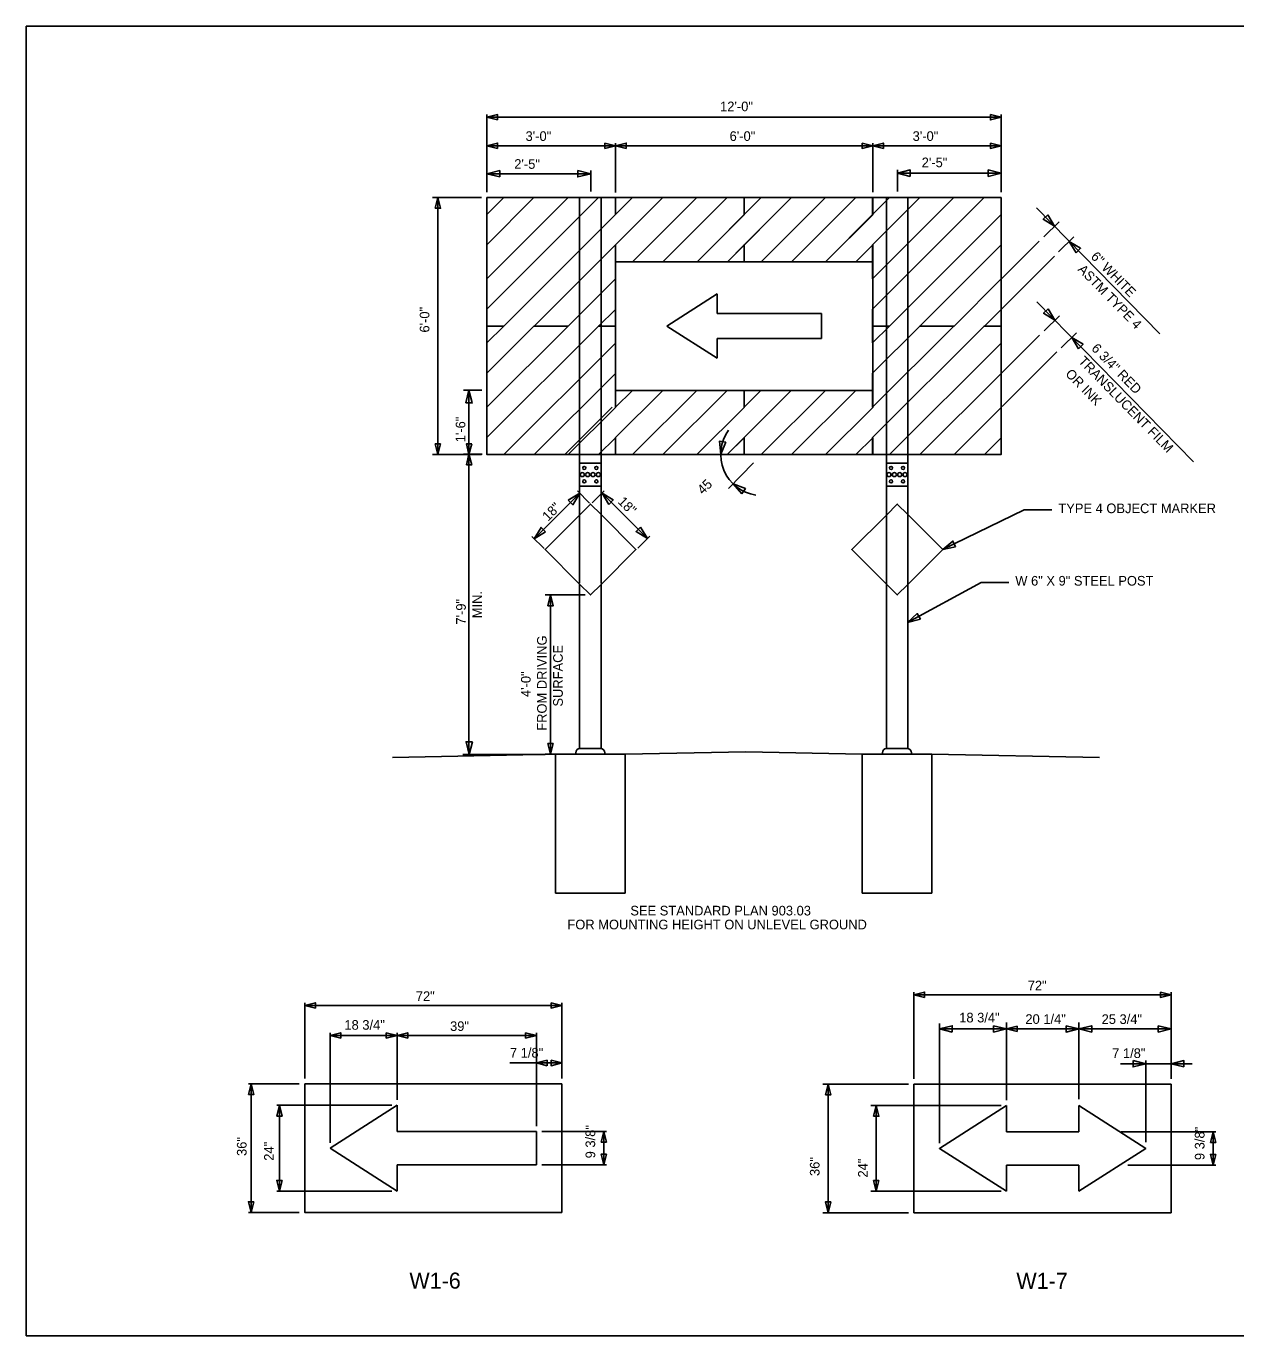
# Model space of a CAD drawing. Extents: x -439.1 to -407.9, y -458.1 to -437.7.
# Drawn here: x -439.11 to -420.29, y -458.05 to -437.68 of the extents above; entities that cross this region are included whole.
import ezdxf

# ---------------------------------------------------------------- set-up
doc = ezdxf.new("R2010")
doc.units = 0
for name, color, linetype in [('Draft_Named_Boundary', 7, 'Continuous'), ('Level 4', 7, 'Continuous'), ('Level 45', 7, 'Continuous')]:
    doc.layers.add(name, color=color, linetype=linetype)

msp = doc.modelspace()

# ---------------------------------------------------------------- linework, layer by layer
at = {"layer": 'Draft_Named_Boundary'}
msp.add_lwpolyline([(-439.109, -458.051), (-407.859, -458.051), (-407.859, -437.676), (-439.109, -437.676)], close=True, dxfattribs=at)
at = {"layer": 'Level 4'}
for p, q in [((-431.681, -440.342), (-431.943, -440.604)), ((-431.21, -440.342), (-431.943, -441.075)), ((-430.679, -440.342), (-431.943, -441.605)), ((-430.208, -440.342), (-431.943, -442.077)), ((-429.678, -440.342), (-429.941, -440.605)), ((-428.676, -440.342), (-429.675, -441.342)), ((-428.204, -440.342), (-429.204, -441.342)), ((-427.678, -440.342), (-427.941, -440.605)), ((-427.206, -440.342), (-427.941, -441.076)), ((-426.676, -440.342), (-427.675, -441.342)), ((-426.204, -440.342), (-427.204, -441.342)), ((-425.681, -440.342), (-425.943, -440.604)), ((-425.21, -440.342), (-425.943, -441.075)), ((-424.679, -440.342), (-425.943, -441.605)), ((-424.208, -440.342), (-425.943, -442.077)), ((-423.393, -440.502), (-421.475, -442.46)), ((-429.943, -440.607), (-431.678, -442.342)), ((-427.941, -440.609), (-428.674, -441.342)), ((-425.941, -440.609), (-426.674, -441.342)), ((-423.943, -440.607), (-425.678, -442.342)), ((-423.28, -440.951), (-423.042, -440.718)), ((-427.941, -441.08), (-428.202, -441.342)), ((-425.941, -441.08), (-426.202, -441.342)), ((-423.943, -441.079), (-425.206, -442.342)), ((-423.938, -441.607), (-423.352, -441.021)), ((-423.049, -441.187), (-422.811, -440.954)), ((-423.938, -442.079), (-423.112, -441.253)), ((-429.943, -441.609), (-430.676, -442.342)), ((-423.943, -441.609), (-424.676, -442.342)), ((-428.362, -441.842), (-429.144, -442.342)), ((-428.362, -442.146), (-428.362, -441.842)), ((-429.943, -442.081), (-430.204, -442.342)), ((-423.386, -441.964), (-420.951, -444.452)), ((-426.737, -442.146), (-428.362, -442.146)), ((-426.737, -442.537), (-426.737, -442.146)), ((-423.273, -442.413), (-423.035, -442.18)), ((-431.681, -442.342), (-431.943, -442.604)), ((-431.21, -442.342), (-431.943, -443.075)), ((-430.679, -442.342), (-431.943, -443.605)), ((-430.208, -442.342), (-431.943, -444.077)), ((-429.144, -442.342), (-428.362, -442.842)), ((-428.362, -442.842), (-428.362, -442.537)), ((-428.362, -442.537), (-426.737, -442.537)), ((-425.681, -442.342), (-425.943, -442.604)), ((-425.21, -442.342), (-425.943, -443.075)), ((-424.679, -442.342), (-425.943, -443.605)), ((-424.208, -442.342), (-425.943, -444.077)), ((-423.931, -443.069), (-423.344, -442.483)), ((-423.011, -442.681), (-422.773, -442.447)), ((-429.943, -442.607), (-431.678, -444.342)), ((-423.943, -442.607), (-425.678, -444.342)), ((-423.926, -443.595), (-423.075, -442.744)), ((-429.943, -443.079), (-431.206, -444.342)), ((-423.943, -443.079), (-425.206, -444.342)), ((-429.679, -443.342), (-429.941, -443.603)), ((-429.208, -443.342), (-429.941, -444.075)), ((-428.677, -443.342), (-429.678, -444.342)), ((-428.206, -443.342), (-429.206, -444.342)), ((-427.679, -443.342), (-427.941, -443.603)), ((-427.208, -443.342), (-427.941, -444.075)), ((-426.677, -443.342), (-427.678, -444.342)), ((-426.206, -443.342), (-427.206, -444.342)), ((-429.993, -443.603), (-430.726, -444.336)), ((-427.941, -443.607), (-428.676, -444.342)), ((-425.941, -443.607), (-426.676, -444.342)), ((-423.943, -443.609), (-424.676, -444.342)), ((-429.943, -444.081), (-430.204, -444.342)), ((-427.941, -444.078), (-428.204, -444.342)), ((-425.941, -444.078), (-426.204, -444.342)), ((-423.943, -444.081), (-424.204, -444.342)), ((-432.221, -444.342), (-432.221, -448.957)), ((-430.501, -444.476), (-430.501, -444.83)), ((-430.167, -444.476), (-430.501, -444.476)), ((-430.167, -444.476), (-430.167, -444.83)), ((-427.795, -444.47), (-428.182, -444.866)), ((-425.729, -444.476), (-425.729, -444.83)), ((-425.729, -444.476), (-425.396, -444.476)), ((-425.396, -444.476), (-425.396, -444.83)), ((-430.167, -444.83), (-430.501, -444.83)), ((-425.729, -444.83), (-425.396, -444.83)), ((-430.874, -449.004), (-433.413, -449.055)), ((-430.584, -449.004), (-431.035, -449.004)), ((-430.874, -449.004), (-430.874, -451.164)), ((-430.874, -449.004), (-429.794, -449.004)), ((-430.561, -448.979), (-430.561, -449.004)), ((-430.496, -448.914), (-430.174, -448.914)), ((-430.447, -448.914), (-430.222, -448.914)), ((-430.11, -448.979), (-430.11, -449.004)), ((-429.794, -449.004), (-429.794, -451.164)), ((-426.103, -449.004), (-426.103, -451.164)), ((-426.103, -449.004), (-425.023, -449.004)), ((-425.789, -448.979), (-425.789, -449.004)), ((-425.725, -448.914), (-425.403, -448.914)), ((-425.675, -448.914), (-425.45, -448.914)), ((-425.338, -448.979), (-425.338, -449.004)), ((-425.023, -449.004), (-422.414, -449.055)), ((-425.023, -449.004), (-425.023, -451.164)), ((-430.874, -451.164), (-429.794, -451.164)), ((-426.103, -451.164), (-425.023, -451.164)), ((-433.34, -454.465), (-434.382, -455.132)), ((-433.34, -454.871), (-433.34, -454.465)), ((-423.862, -454.469), (-424.904, -455.136)), ((-423.862, -454.875), (-423.862, -454.469)), ((-422.733, -454.875), (-422.733, -454.469)), ((-422.733, -454.469), (-421.691, -455.136)), ((-431.173, -454.871), (-433.34, -454.871)), ((-431.173, -455.392), (-431.173, -454.871)), ((-422.733, -454.875), (-423.862, -454.875)), ((-423.862, -454.875), (-422.733, -454.875)), ((-434.382, -455.132), (-433.34, -455.799)), ((-424.904, -455.136), (-423.862, -455.802)), ((-424.9, -455.138), (-424.9, -455.133)), ((-421.691, -455.136), (-422.733, -455.802)), ((-421.695, -455.138), (-421.695, -455.133)), ((-433.34, -455.799), (-433.34, -455.392)), ((-433.34, -455.392), (-431.173, -455.392)), ((-423.862, -455.802), (-423.862, -455.396)), ((-423.862, -455.396), (-422.733, -455.396)), ((-422.733, -455.396), (-423.862, -455.396)), ((-422.733, -455.802), (-422.733, -455.396))]:
    msp.add_line(p, q, dxfattribs=at)
for points in [[(-431.943, -440.342), (-423.943, -440.342), (-423.943, -444.342), (-431.943, -444.342)], [(-431.943, -442.077), (-431.943, -442.342), (-431.678, -442.342), (-429.943, -440.607), (-429.943, -440.342), (-430.208, -440.342)], [(-431.943, -441.605), (-431.943, -441.075), (-431.21, -440.342), (-430.679, -440.342)], [(-431.943, -440.604), (-431.943, -440.342), (-431.681, -440.342)], [(-430.167, -440.342), (-430.167, -444.337), (-430.501, -444.337), (-430.501, -440.342)], [(-429.678, -440.342), (-429.941, -440.342), (-429.941, -440.605)], [(-429.206, -440.342), (-429.941, -441.076), (-429.941, -441.342), (-429.675, -441.342), (-428.676, -440.342)], [(-428.204, -440.342), (-427.678, -440.342), (-428.674, -441.342), (-429.204, -441.342)], [(-428.202, -441.342), (-427.675, -441.342), (-426.676, -440.342), (-427.206, -440.342)], [(-427.204, -441.342), (-426.674, -441.342), (-425.943, -440.604), (-425.943, -440.342), (-426.204, -440.342)], [(-425.943, -442.077), (-425.943, -442.342), (-425.678, -442.342), (-423.943, -440.607), (-423.943, -440.342), (-424.208, -440.342)], [(-425.943, -441.605), (-425.943, -441.075), (-425.21, -440.342), (-424.679, -440.342)], [(-425.943, -440.604), (-425.943, -440.342), (-425.681, -440.342)], [(-425.396, -440.342), (-425.396, -444.338), (-425.729, -444.338), (-425.729, -440.342)], [(-423.218, -440.61), (-423.113, -440.788), (-423.289, -440.68)], [(-431.206, -442.342), (-430.676, -442.342), (-429.943, -441.609), (-429.943, -441.079)], [(-428.202, -441.342), (-427.941, -441.342), (-427.941, -441.08)], [(-426.202, -441.342), (-425.941, -441.342), (-425.941, -441.08)], [(-425.206, -442.342), (-424.676, -442.342), (-423.943, -441.609), (-423.943, -441.079)], [(-422.778, -441.201), (-422.883, -441.024), (-422.707, -441.131)], [(-429.941, -441.342), (-425.941, -441.342), (-425.941, -443.342), (-429.941, -443.342)], [(-430.204, -442.342), (-429.943, -442.342), (-429.943, -442.081)], [(-424.204, -442.342), (-423.943, -442.342), (-423.943, -442.081)], [(-423.21, -442.072), (-423.106, -442.25), (-423.282, -442.142)], [(-431.943, -444.077), (-431.943, -444.342), (-431.678, -444.342), (-429.943, -442.607), (-429.943, -442.342), (-430.208, -442.342)], [(-431.943, -443.605), (-431.943, -443.075), (-431.21, -442.342), (-430.679, -442.342)], [(-431.943, -442.604), (-431.943, -442.342), (-431.681, -442.342)], [(-425.943, -444.077), (-425.943, -444.342), (-425.678, -444.342), (-423.943, -442.607), (-423.943, -442.342), (-424.208, -442.342)], [(-425.943, -443.605), (-425.943, -443.075), (-425.21, -442.342), (-424.679, -442.342)], [(-425.943, -442.604), (-425.943, -442.342), (-425.681, -442.342)], [(-422.74, -442.695), (-422.845, -442.517), (-422.669, -442.625)], [(-431.206, -444.342), (-430.676, -444.342), (-429.943, -443.609), (-429.943, -443.079)], [(-425.206, -444.342), (-424.676, -444.342), (-423.943, -443.609), (-423.943, -443.079)], [(-429.941, -443.603), (-429.941, -443.342), (-429.679, -443.342)], [(-429.941, -444.075), (-429.208, -443.342), (-428.677, -443.342), (-429.678, -444.342), (-429.941, -444.342)], [(-429.206, -444.342), (-428.676, -444.342), (-427.941, -443.607), (-427.941, -443.342), (-428.206, -443.342)], [(-428.204, -444.342), (-427.678, -444.342), (-426.677, -443.342), (-427.208, -443.342)], [(-427.941, -443.603), (-427.941, -443.342), (-427.679, -443.342)], [(-427.206, -444.342), (-426.676, -444.342), (-425.941, -443.607), (-425.941, -443.342), (-426.206, -443.342)], [(-430.204, -444.342), (-429.943, -444.342), (-429.943, -444.081)], [(-428.224, -444.146), (-428.305, -444.335), (-428.323, -444.13)], [(-425.941, -444.078), (-426.204, -444.342), (-425.943, -444.342)], [(-424.204, -444.342), (-423.943, -444.342), (-423.943, -444.081)], [(-427.979, -444.951), (-428.112, -444.795), (-427.921, -444.87)], [(-424.651, -445.776), (-424.852, -445.818), (-424.694, -445.686)], [(-425.199, -446.903), (-425.399, -446.955), (-425.247, -446.815)], [(-434.777, -454.132), (-430.777, -454.132), (-430.777, -456.132), (-434.777, -456.132)], [(-425.299, -454.136), (-421.299, -454.136), (-421.299, -456.136), (-425.299, -456.136)]]:
    msp.add_lwpolyline(points, close=True, dxfattribs=at)
for points in [[(-429.206, -440.342), (-429.941, -441.076), (-429.941, -441.342), (-429.675, -441.342), (-428.676, -440.342)], [(-429.678, -440.342), (-429.941, -440.605), (-429.941, -440.342)], [(-428.204, -440.342), (-429.204, -441.342), (-428.674, -441.342), (-427.941, -440.609), (-427.941, -440.342)], [(-427.206, -440.342), (-427.941, -441.076), (-427.941, -441.342), (-427.675, -441.342), (-426.676, -440.342)], [(-427.678, -440.342), (-427.941, -440.605), (-427.941, -440.342)], [(-426.204, -440.342), (-427.204, -441.342), (-426.674, -441.342), (-425.941, -440.609), (-425.941, -440.342)], [(-429.941, -444.342), (-429.941, -444.075), (-429.208, -443.342), (-428.677, -443.342), (-429.678, -444.342)], [(-428.676, -444.342), (-427.941, -443.607), (-427.941, -443.342), (-428.206, -443.342), (-429.206, -444.342)], [(-427.941, -444.342), (-427.941, -444.075), (-427.208, -443.342), (-426.677, -443.342), (-427.678, -444.342)], [(-426.676, -444.342), (-425.941, -443.607), (-425.941, -443.342), (-426.206, -443.342), (-427.206, -444.342)], [(-425.941, -444.342), (-425.941, -444.078), (-426.204, -444.342)], [(-430.501, -444.337), (-430.501, -445.281)], [(-430.167, -445.275), (-430.167, -444.337)], [(-425.729, -444.338), (-425.729, -445.281)], [(-425.396, -445.275), (-425.396, -444.338)], [(-430.167, -445.275), (-430.331, -445.111), (-430.501, -445.281)], [(-425.396, -445.275), (-425.559, -445.111), (-425.729, -445.281)], [(-430.501, -445.281), (-431.038, -445.818), (-430.501, -446.356)], [(-430.501, -445.281), (-430.501, -446.342)], [(-430.167, -446.348), (-430.167, -445.275)], [(-430.167, -446.362), (-429.624, -445.818), (-430.167, -445.275)], [(-425.729, -445.281), (-426.267, -445.818), (-425.729, -446.356)], [(-425.729, -445.281), (-425.729, -446.356)], [(-425.396, -446.362), (-425.396, -445.275)], [(-425.396, -446.362), (-424.852, -445.818), (-425.396, -445.275)], [(-424.853, -445.819), (-423.583, -445.202), (-423.153, -445.202)], [(-430.501, -446.356), (-430.331, -446.525), (-430.167, -446.362)], [(-430.501, -446.356), (-430.501, -448.914)], [(-430.167, -448.914), (-430.167, -446.362)], [(-425.729, -446.356), (-425.559, -446.525), (-425.396, -446.362)], [(-425.729, -446.356), (-425.729, -448.914)], [(-425.399, -446.955), (-424.253, -446.33), (-423.823, -446.33)], [(-425.396, -448.915), (-425.396, -446.362)], [(-429.794, -449.004), (-427.913, -448.967), (-426.103, -449.004)]]:
    msp.add_lwpolyline(points, dxfattribs=at)
for centre, radius in [((-430.428, -444.548), 0.0243), ((-430.24, -444.548), 0.0243), ((-425.656, -444.548), 0.0243), ((-425.469, -444.548), 0.0243), ((-430.459, -444.653), 0.0313), ((-430.428, -444.757), 0.0243), ((-430.376, -444.653), 0.0313), ((-430.292, -444.653), 0.0313), ((-430.24, -444.757), 0.0243), ((-430.209, -444.653), 0.0313), ((-425.688, -444.653), 0.0313), ((-425.656, -444.757), 0.0243), ((-425.604, -444.653), 0.0313), ((-425.521, -444.653), 0.0313), ((-425.469, -444.757), 0.0243), ((-425.438, -444.653), 0.0313)]:
    msp.add_circle(centre, radius, dxfattribs=at)
for centre, radius, start, end in [((-427.663, -444.336), 0.642, 144.1907, 261.2849), ((-430.496, -448.979), 0.0648, 90, 180), ((-430.174, -448.979), 0.0648, 0, 90), ((-425.725, -448.979), 0.0648, 90, 180), ((-425.403, -448.979), 0.0648, 0, 90)]:
    msp.add_arc(centre, radius, start, end, dxfattribs=at)
at = {"layer": 'Level 45'}
for p, q in [((-431.943, -440.259), (-431.943, -439.05)), ((-423.943, -440.259), (-423.943, -439.05)), ((-431.943, -439.091), (-423.943, -439.091)), ((-431.943, -440.259), (-431.943, -439.298)), ((-423.943, -440.259), (-423.943, -439.298)), ((-431.943, -439.537), (-429.941, -439.537)), ((-429.941, -440.264), (-429.941, -439.495)), ((-429.941, -439.537), (-425.94, -439.537)), ((-425.94, -440.257), (-425.94, -439.495)), ((-425.94, -439.537), (-423.943, -439.537)), ((-431.943, -440.242), (-431.943, -439.872)), ((-423.943, -440.242), (-423.943, -439.862)), ((-431.943, -439.972), (-430.328, -439.972)), ((-430.328, -440.246), (-430.328, -439.922)), ((-425.557, -440.246), (-425.557, -439.912)), ((-423.943, -439.962), (-425.557, -439.962)), ((-432.026, -440.342), (-432.787, -440.342)), ((-432.704, -440.342), (-432.704, -444.342)), ((-432.023, -443.337), (-432.304, -443.337)), ((-432.221, -443.337), (-432.221, -444.342)), ((-432.026, -444.342), (-432.787, -444.342)), ((-432.043, -444.342), (-432.75, -444.342)), ((-432.016, -444.334), (-432.304, -444.334)), ((-431.206, -445.65), (-430.499, -444.943)), ((-430.347, -445.095), (-430.535, -444.907)), ((-430.304, -445.09), (-430.117, -444.904)), ((-430.152, -444.939), (-429.445, -445.646)), ((-431.054, -445.802), (-431.242, -445.615)), ((-429.597, -445.797), (-429.41, -445.611)), ((-430.414, -446.525), (-431.035, -446.525)), ((-430.952, -446.525), (-430.952, -449.004)), ((-431.034, -449.009), (-432.316, -449.009)), ((-425.299, -454.052), (-425.299, -452.703)), ((-421.299, -454.052), (-421.299, -452.703)), ((-434.777, -454.049), (-434.777, -452.868)), ((-434.777, -452.91), (-430.777, -452.91)), ((-430.777, -454.049), (-430.777, -452.868)), ((-425.299, -452.744), (-421.299, -452.744)), ((-434.382, -455.049), (-434.382, -453.337)), ((-433.34, -454.382), (-433.34, -453.337)), ((-433.34, -454.382), (-433.34, -453.337)), ((-431.173, -454.788), (-431.173, -453.337)), ((-424.904, -455.052), (-424.904, -453.193)), ((-424.904, -453.276), (-423.862, -453.276)), ((-423.862, -454.369), (-423.862, -453.176)), ((-423.862, -454.386), (-423.862, -453.193)), ((-423.862, -453.276), (-422.733, -453.276)), ((-422.733, -454.369), (-422.733, -453.176)), ((-422.733, -454.369), (-422.733, -453.176)), ((-422.733, -453.276), (-421.299, -453.276)), ((-421.299, -454.036), (-421.299, -453.176)), ((-434.382, -453.378), (-433.34, -453.378)), ((-433.34, -453.378), (-431.173, -453.378)), ((-431.173, -454.788), (-431.173, -453.723)), ((-430.777, -454.049), (-430.777, -453.723)), ((-431.586, -453.806), (-430.777, -453.806)), ((-420.97, -453.818), (-422.089, -453.818)), ((-421.691, -455.036), (-421.691, -453.768)), ((-434.861, -454.132), (-435.653, -454.132)), ((-435.612, -456.132), (-435.612, -454.132)), ((-425.383, -454.136), (-426.718, -454.136)), ((-426.635, -456.136), (-426.635, -454.136)), ((-433.423, -454.465), (-435.212, -454.465)), ((-435.171, -455.799), (-435.171, -454.465)), ((-423.945, -454.469), (-425.969, -454.469)), ((-425.886, -455.802), (-425.886, -454.469)), ((-424.904, -455.136), (-423.862, -454.469)), ((-423.862, -454.469), (-423.862, -454.875)), ((-422.733, -454.875), (-422.733, -454.469)), ((-422.733, -454.469), (-421.691, -455.136)), ((-431.09, -454.871), (-430.083, -454.871)), ((-430.125, -455.392), (-430.125, -454.871)), ((-423.862, -454.875), (-422.733, -454.875)), ((-422.074, -454.875), (-420.605, -454.875)), ((-420.647, -455.396), (-420.647, -454.875)), ((-423.862, -455.802), (-424.904, -455.136)), ((-421.691, -455.136), (-422.733, -455.802)), ((-431.09, -455.392), (-430.083, -455.392)), ((-422.733, -455.396), (-423.862, -455.396)), ((-423.862, -455.396), (-423.862, -455.802)), ((-422.733, -455.802), (-422.733, -455.396)), ((-421.973, -455.396), (-420.605, -455.396)), ((-433.423, -455.799), (-435.212, -455.799)), ((-423.945, -455.802), (-425.969, -455.802)), ((-434.861, -456.132), (-435.653, -456.132)), ((-425.383, -456.136), (-426.718, -456.136))]:
    msp.add_line(p, q, dxfattribs=at)
for points in [[(-431.776, -439.133), (-431.943, -439.091), (-431.776, -439.05)], [(-424.109, -439.05), (-423.943, -439.091), (-424.109, -439.133)], [(-431.776, -439.578), (-431.943, -439.537), (-431.776, -439.495)], [(-430.107, -439.495), (-429.941, -439.537), (-430.107, -439.578)], [(-429.774, -439.578), (-429.941, -439.537), (-429.774, -439.495)], [(-426.107, -439.495), (-425.94, -439.537), (-426.107, -439.578)], [(-425.774, -439.578), (-425.94, -439.537), (-425.774, -439.495)], [(-424.109, -439.495), (-423.943, -439.537), (-424.109, -439.578)], [(-431.743, -440.022), (-431.943, -439.972), (-431.743, -439.922)], [(-430.528, -439.922), (-430.328, -439.972), (-430.528, -440.022)], [(-425.357, -440.012), (-425.557, -439.962), (-425.357, -439.912)], [(-424.143, -439.912), (-423.943, -439.962), (-424.143, -440.012)], [(-432.745, -440.509), (-432.704, -440.342), (-432.662, -440.509)], [(-432.271, -443.537), (-432.221, -443.337), (-432.171, -443.537)], [(-432.662, -444.175), (-432.704, -444.342), (-432.745, -444.175)], [(-432.179, -444.175), (-432.221, -444.342), (-432.262, -444.175)], [(-432.262, -444.501), (-432.221, -444.334), (-432.179, -444.501)], [(-430.676, -445.049), (-430.499, -444.943), (-430.605, -445.12)], [(-430.046, -445.116), (-430.152, -444.939), (-429.976, -445.045)], [(-431.03, -445.544), (-431.206, -445.65), (-431.1, -445.473)], [(-429.551, -445.469), (-429.445, -445.646), (-429.622, -445.54)], [(-430.994, -446.692), (-430.952, -446.525), (-430.91, -446.692)], [(-432.166, -448.809), (-432.216, -449.009), (-432.266, -448.809)], [(-430.91, -448.837), (-430.952, -449.004), (-430.994, -448.837)], [(-425.133, -452.786), (-425.299, -452.744), (-425.133, -452.703)], [(-421.466, -452.703), (-421.299, -452.744), (-421.466, -452.786)], [(-434.611, -452.952), (-434.777, -452.91), (-434.611, -452.868)], [(-430.944, -452.868), (-430.777, -452.91), (-430.944, -452.952)], [(-434.215, -453.42), (-434.382, -453.378), (-434.215, -453.337)], [(-433.507, -453.337), (-433.34, -453.378), (-433.507, -453.42)], [(-433.173, -453.42), (-433.34, -453.378), (-433.173, -453.337)], [(-431.34, -453.337), (-431.173, -453.378), (-431.34, -453.42)], [(-424.704, -453.326), (-424.904, -453.276), (-424.704, -453.226)], [(-424.062, -453.226), (-423.862, -453.276), (-424.062, -453.326)], [(-423.695, -453.318), (-423.862, -453.276), (-423.695, -453.234)], [(-422.933, -453.226), (-422.733, -453.276), (-422.933, -453.326)], [(-422.533, -453.326), (-422.733, -453.276), (-422.533, -453.226)], [(-421.499, -453.226), (-421.299, -453.276), (-421.499, -453.326)], [(-431.007, -453.848), (-431.173, -453.806), (-431.007, -453.764)], [(-430.944, -453.764), (-430.777, -453.806), (-430.944, -453.848)], [(-421.891, -453.768), (-421.691, -453.818), (-421.891, -453.868)], [(-421.099, -453.868), (-421.299, -453.818), (-421.099, -453.768)], [(-435.653, -454.299), (-435.612, -454.132), (-435.57, -454.299)], [(-426.677, -454.302), (-426.635, -454.136), (-426.593, -454.302)], [(-435.212, -454.632), (-435.171, -454.465), (-435.129, -454.632)], [(-425.928, -454.636), (-425.886, -454.469), (-425.844, -454.636)], [(-430.166, -455.038), (-430.125, -454.871), (-430.083, -455.038)], [(-420.689, -455.042), (-420.647, -454.875), (-420.605, -455.042)], [(-430.083, -455.226), (-430.125, -455.392), (-430.166, -455.226)], [(-420.605, -455.229), (-420.647, -455.396), (-420.689, -455.229)], [(-435.129, -455.632), (-435.171, -455.799), (-435.212, -455.632)], [(-425.844, -455.636), (-425.886, -455.802), (-425.928, -455.636)], [(-435.57, -455.965), (-435.612, -456.132), (-435.653, -455.965)], [(-426.593, -455.969), (-426.635, -456.136), (-426.677, -455.969)]]:
    msp.add_lwpolyline(points, close=True, dxfattribs=at)

# ---------------------------------------------------------------- texts
at = {"layer": 'Level 4'}
msp.add_text('45', height=0.15, rotation=44.6693, dxfattribs=at).set_placement((-428.582, -444.972))
for s, height, p in [('TYPE 4 OBJECT MARKER', 0.15, (-423.053, -445.252)), ('SEE STANDARD PLAN 903.03', 0.15, (-429.711, -451.511)), ('FOR MOUNTING HEIGHT ON UNLEVEL GROUND', 0.15, (-430.69, -451.727)), ('W1-6', 0.25, (-433.148, -457.317)), ('W1-7', 0.25, (-423.706, -457.321))]:
    msp.add_text(s, height=height, dxfattribs=at).set_placement(p)
at = {"layer": 'Level 45'}
for s, p in [('12\'-0"', (-428.315, -438.999)), ('3\'-0"', (-431.341, -439.461)), ('6\'-0"', (-428.167, -439.461)), ('3\'-0"', (-425.32, -439.461)), ('2\'-5"', (-431.517, -439.895)), ('2\'-5"', (-425.179, -439.87)), ('W 6" X 9" STEEL POST', (-423.723, -446.379)), ('72"', (-423.529, -452.676)), ('72"', (-433.048, -452.842)), ('18 3/4"', (-434.159, -453.289)), ('18 3/4"', (-424.595, -453.175)), ('20 1/4"', (-423.566, -453.198)), ('25 3/4"', (-422.38, -453.199)), ('39"', (-432.515, -453.308)), ('7 1/8"', (-431.584, -453.722)), ('7 1/8"', (-422.216, -453.729))]:
    msp.add_text(s, height=0.15, dxfattribs=at).set_placement(p)
for s, rotation, p in [('6" WHITE', 314.4047, (-422.558, -441.272)), ('ASTM TYPE 4', 314.4047, (-422.761, -441.47)), ('6\'-0"', 90, (-432.837, -442.442)), ('6 3/4" RED', 314.383, (-422.549, -442.7)), ('TRANSLUCENT FILM', 314.383, (-422.752, -442.898)), ('OR INK', 314.383, (-422.954, -443.096)), ('1\'-6"', 90, (-432.278, -444.15)), ('18"', 45, (-430.992, -445.387)), ('18"', 315, (-429.916, -445.084)), ('7\'-9"', 90, (-432.271, -446.986)), ('MIN.', 90, (-432.021, -446.887)), ('FROM DRIVING', 90, (-431.012, -448.637)), ('SURFACE', 90, (-430.762, -448.261)), ('4\'-0"', 90, (-431.262, -448.113)), ('36"', 90, (-435.681, -455.253)), ('9 3/8"', 90, (-430.258, -455.29)), ('9 3/8"', 90, (-420.78, -455.317)), ('24"', 90, (-435.258, -455.327)), ('36"', 90, (-426.768, -455.565)), ('24"', 90, (-426.019, -455.588))]:
    msp.add_text(s, height=0.15, rotation=rotation, dxfattribs=at).set_placement(p)

doc.saveas('drawing.dxf')
